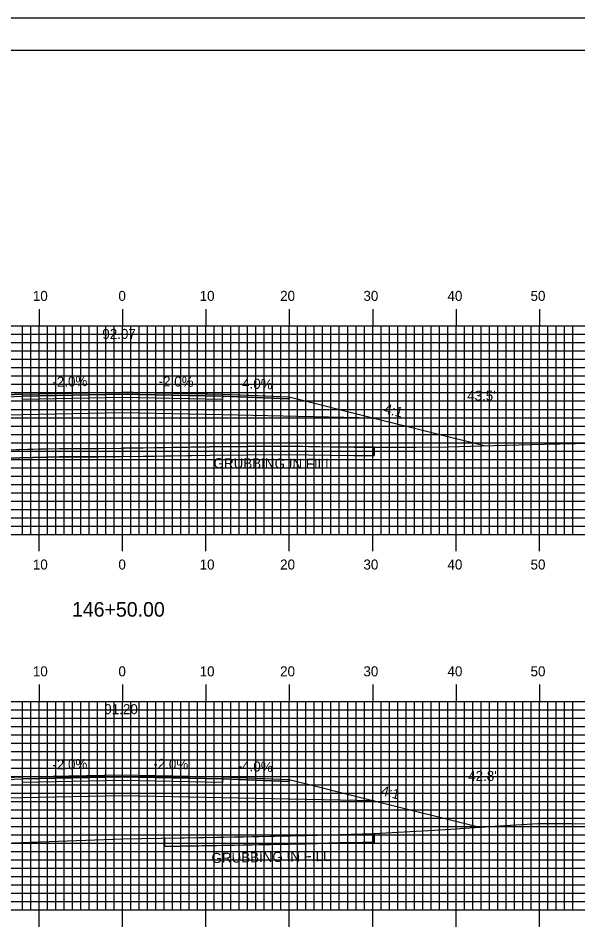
# Model space of a CAD drawing. Extents: x 1777531 to 1777875, y 442591 to 442811.
# Drawn here: x 1777684.8 to 1777751.9, y 442701.2 to 442810.5 of the extents above; entities that cross this region are included whole.
import ezdxf

# ---------------------------------------------------------------- set-up
doc = ezdxf.new("R2010")
doc.units = 0
for name, color, linetype in [('ANNOTATION', 7, 'Continuous'), ('BORDER', 7, 'Continuous'), ('D_Roadway_Centerline', 7, 'Continuous'), ('D_Roadway_Centerline_Text', 7, 'Continuous'), ('D_Roadway_Edge_Shoulder', 7, 'Continuous'), ('D_Roadway_Edge_TW', 7, 'Continuous'), ('D_Roadway_Pavement', 7, 'Continuous'), ('D_Roadway_SlopeLines', 7, 'Continuous'), ('D_Roadway_SubGrade', 7, 'Continuous'), ('D_Text_Standard', 7, 'Continuous'), ('GRUBBING IN FILL', 7, 'Continuous'), ('H_V ANNOTATION', 7, 'Continuous'), ('MAJOR', 7, 'Continuous'), ('MINOR', 7, 'Continuous'), ('PLOT BOUNDARY', 7, 'Continuous'), ('S_Roadway_Centerline', 7, 'Continuous')]:
    doc.layers.add(name, color=color, linetype=linetype)

msp = doc.modelspace()

# ---------------------------------------------------------------- linework, layer by layer
at = {"layer": 'BORDER'}
msp.add_lwpolyline([(1777547.68, 442596.67), (1777867.68, 442596.67), (1777867.68, 442806.67), (1777547.68, 442806.67)], close=True, dxfattribs=at)
at = {"layer": 'D_Roadway_Centerline'}
for points in [[(1777647.68, 442757.78), (1777665.28, 442762.18), (1777666.08, 442762.38), (1777667.1, 442762.63), (1777677.28, 442765.18), (1777680.02, 442765.29), (1777685.28, 442765.5), (1777697.28, 442765.74), (1777698.56, 442765.71), (1777709.28, 442765.5), (1777713.52, 442765.33), (1777717.28, 442765.18), (1777727.45, 442762.63), (1777740.8, 442759.3)], [(1777645.53, 442711.37), (1777665.28, 442716.3), (1777665.54, 442716.37), (1777667.1, 442716.76), (1777677.28, 442719.3), (1777680.25, 442719.42), (1777685.28, 442719.62), (1777690.81, 442719.73), (1777697.28, 442719.86), (1777697.28, 442719.86), (1777709.28, 442719.62), (1777717.28, 442719.3), (1777727.45, 442716.76), (1777740.11, 442713.59), (1777740.11, 442713.59)]]:
    msp.add_lwpolyline(points, dxfattribs=at)
at = {"layer": 'D_Roadway_Edge_Shoulder'}
for points in [[(1777685.28, 442765.5), (1777677.28, 442765.18), (1777677.28, 442764.93), (1777685.28, 442765.25)], [(1777709.28, 442765.5), (1777717.28, 442765.18), (1777717.28, 442764.93), (1777709.28, 442765.25)], [(1777685.28, 442719.62), (1777677.28, 442719.3), (1777677.28, 442719.05), (1777685.28, 442719.37)], [(1777709.28, 442719.62), (1777717.28, 442719.3), (1777717.28, 442719.05), (1777709.28, 442719.37)]]:
    msp.add_lwpolyline(points, close=True, dxfattribs=at)
at = {"layer": 'D_Roadway_Edge_TW'}
for points in [[(1777685.28, 442765.25), (1777685.28, 442765.5), (1777697.28, 442765.74), (1777709.28, 442765.5), (1777709.28, 442765.25), (1777697.28, 442765.49)], [(1777685.28, 442719.37), (1777685.28, 442719.62), (1777697.28, 442719.86), (1777709.28, 442719.62), (1777709.28, 442719.37), (1777697.28, 442719.61)]]:
    msp.add_lwpolyline(points, close=True, dxfattribs=at)
at = {"layer": 'D_Roadway_Pavement'}
for points in [[(1777685.28, 442764.83), (1777685.28, 442765.25), (1777697.28, 442765.49), (1777709.28, 442765.25), (1777709.28, 442764.83), (1777697.28, 442765.07)], [(1777685.28, 442718.96), (1777685.28, 442719.37), (1777697.28, 442719.61), (1777709.28, 442719.37), (1777709.28, 442718.96), (1777697.28, 442719.2)]]:
    msp.add_lwpolyline(points, close=True, dxfattribs=at)
at = {"layer": 'D_Roadway_SlopeLines'}
for points in [[(1777717.28, 442765.18), (1777727.45, 442762.63), (1777740.8, 442759.3)], [(1777717.28, 442719.3), (1777727.45, 442716.76), (1777740.11, 442713.59)]]:
    msp.add_lwpolyline(points, dxfattribs=at)
at = {"layer": 'D_Roadway_SubGrade'}
for points in [[(1777685.28, 442763), (1777667.1, 442762.63), (1777677.28, 442765.18), (1777677.28, 442764.93), (1777685.28, 442765.25), (1777697.28, 442765.49), (1777709.28, 442765.25), (1777717.28, 442764.93), (1777717.28, 442765.18), (1777727.45, 442762.63), (1777709.28, 442763), (1777697.28, 442763.24)], [(1777685.28, 442717.12), (1777667.1, 442716.76), (1777677.28, 442719.3), (1777677.28, 442719.05), (1777685.28, 442719.37), (1777697.28, 442719.61), (1777709.28, 442719.37), (1777717.28, 442719.05), (1777717.28, 442719.3), (1777727.45, 442716.76), (1777709.28, 442717.12), (1777697.28, 442717.36)]]:
    msp.add_lwpolyline(points, close=True, dxfattribs=at)
at = {"layer": 'GRUBBING IN FILL'}
for p, q in [((1777727.45, 442759.13), (1777727.45, 442758.13)), ((1777727.45, 442759.13), (1777727.45, 442758.13)), ((1777702.32, 442712.26), (1777702.32, 442711.26)), ((1777702.32, 442712.26), (1777702.32, 442711.26)), ((1777727.45, 442711.76), (1777727.45, 442712.82)), ((1777727.45, 442711.76), (1777727.45, 442712.82))]:
    msp.add_line(p, q, dxfattribs=at)
for points in [[(1777667.1, 442758.15), (1777669.22, 442758.21), (1777675.28, 442758.49), (1777678.54, 442758.68), (1777681.74, 442758.77), (1777687.32, 442758.92), (1777692.07, 442758.98), (1777697.28, 442759.01), (1777697.28, 442758.01), (1777694.46, 442757.97), (1777689.7, 442757.99), (1777681.78, 442757.77), (1777678.58, 442757.68), (1777672.07, 442757.3), (1777667.1, 442757.15)], [(1777667.1, 442758.15), (1777669.22, 442758.21), (1777675.28, 442758.49), (1777678.54, 442758.68), (1777681.74, 442758.77), (1777687.32, 442758.92), (1777692.07, 442758.98), (1777697.28, 442759.01), (1777697.28, 442758.01), (1777694.46, 442757.97), (1777689.7, 442757.99), (1777681.78, 442757.77), (1777678.58, 442757.68), (1777672.07, 442757.3), (1777667.1, 442757.15)], [(1777697.28, 442758.01), (1777701.1, 442758.07), (1777707.74, 442758.17), (1777716.86, 442758.27), (1777725.04, 442758.12), (1777727.45, 442758.13), (1777727.45, 442759.13), (1777725.05, 442759.12), (1777720.96, 442759.19), (1777716.86, 442759.27), (1777712.3, 442759.22), (1777707.73, 442759.17), (1777701.09, 442759.07), (1777697.28, 442759.01)], [(1777697.28, 442758.01), (1777701.1, 442758.07), (1777707.74, 442758.17), (1777716.86, 442758.27), (1777725.04, 442758.12), (1777727.45, 442758.13), (1777727.45, 442759.13), (1777725.05, 442759.12), (1777720.96, 442759.19), (1777716.86, 442759.27), (1777712.3, 442759.22), (1777707.73, 442759.17), (1777701.09, 442759.07), (1777697.28, 442759.01)], [(1777702.32, 442712.26), (1777711.78, 442712.44), (1777719.29, 442712.59), (1777727.43, 442712.82), (1777727.45, 442712.82), (1777727.45, 442711.76), (1777723.38, 442711.7), (1777719.31, 442711.59), (1777711.8, 442711.44), (1777704.28, 442711.3), (1777702.32, 442711.26)], [(1777702.32, 442712.26), (1777711.78, 442712.44), (1777719.29, 442712.59), (1777727.43, 442712.82), (1777727.45, 442712.82), (1777727.45, 442711.76), (1777723.38, 442711.7), (1777719.31, 442711.59), (1777711.8, 442711.44), (1777704.28, 442711.3), (1777702.32, 442711.26)]]:
    msp.add_lwpolyline(points, close=True, dxfattribs=at)
for points in [[(1777667.1, 442757.15), (1777672.07, 442757.3), (1777678.58, 442757.68), (1777684.98, 442757.85), (1777689.7, 442757.99), (1777694.46, 442757.97), (1777707.74, 442758.17), (1777716.86, 442758.27), (1777725.04, 442758.12), (1777727.45, 442758.13)], [(1777667.1, 442757.15), (1777672.07, 442757.3), (1777678.58, 442757.68), (1777684.98, 442757.85), (1777689.7, 442757.99), (1777694.46, 442757.97), (1777707.74, 442758.17), (1777716.86, 442758.27), (1777725.04, 442758.12), (1777727.45, 442758.13)], [(1777702.32, 442711.26), (1777704.28, 442711.3), (1777719.31, 442711.59), (1777727.45, 442711.82)], [(1777702.32, 442711.26), (1777704.28, 442711.3), (1777719.31, 442711.59), (1777727.45, 442711.82)]]:
    msp.add_lwpolyline(points, dxfattribs=at)
at = {"layer": 'MAJOR'}
for p, q in [((1777687.28, 442775.67), (1777687.28, 442773.67)), ((1777697.28, 442775.67), (1777697.28, 442773.67)), ((1777707.28, 442775.67), (1777707.28, 442773.67)), ((1777717.28, 442775.67), (1777717.28, 442773.67)), ((1777727.28, 442775.67), (1777727.28, 442773.67)), ((1777737.28, 442775.67), (1777737.28, 442773.67)), ((1777747.28, 442775.67), (1777747.28, 442773.67)), ((1777557.28, 442773.67), (1777837.28, 442773.67)), ((1777557.28, 442773.67), (1777837.28, 442773.67)), ((1777687.28, 442748.67), (1777687.28, 442773.67)), ((1777697.28, 442748.67), (1777697.28, 442773.67)), ((1777707.28, 442748.67), (1777707.28, 442773.67)), ((1777717.28, 442748.67), (1777717.28, 442773.67)), ((1777727.28, 442748.67), (1777727.28, 442773.67)), ((1777737.28, 442748.67), (1777737.28, 442773.67)), ((1777747.28, 442748.67), (1777747.28, 442773.67)), ((1777557.28, 442768.67), (1777837.28, 442768.67)), ((1777557.28, 442763.67), (1777837.28, 442763.67)), ((1777557.28, 442758.67), (1777837.28, 442758.67)), ((1777557.28, 442753.67), (1777837.28, 442753.67)), ((1777557.28, 442748.67), (1777837.28, 442748.67)), ((1777557.28, 442748.67), (1777837.28, 442748.67)), ((1777687.28, 442746.66), (1777687.28, 442748.67)), ((1777697.28, 442746.66), (1777697.28, 442748.67)), ((1777707.28, 442746.66), (1777707.28, 442748.67)), ((1777717.28, 442746.66), (1777717.28, 442748.67)), ((1777727.28, 442746.66), (1777727.28, 442748.67)), ((1777737.28, 442746.66), (1777737.28, 442748.67)), ((1777747.28, 442746.66), (1777747.28, 442748.67)), ((1777687.28, 442730.67), (1777687.28, 442728.67)), ((1777697.28, 442730.67), (1777697.28, 442728.67)), ((1777707.28, 442730.67), (1777707.28, 442728.67)), ((1777717.28, 442730.67), (1777717.28, 442728.67)), ((1777727.28, 442730.67), (1777727.28, 442728.67)), ((1777737.28, 442730.67), (1777737.28, 442728.67)), ((1777747.28, 442730.67), (1777747.28, 442728.67)), ((1777557.28, 442728.67), (1777837.28, 442728.67)), ((1777557.28, 442728.67), (1777837.28, 442728.67)), ((1777687.28, 442703.67), (1777687.28, 442728.67)), ((1777697.28, 442703.67), (1777697.28, 442728.67)), ((1777707.28, 442703.67), (1777707.28, 442728.67)), ((1777717.28, 442703.67), (1777717.28, 442728.67)), ((1777727.28, 442703.67), (1777727.28, 442728.67)), ((1777737.28, 442703.67), (1777737.28, 442728.67)), ((1777747.28, 442703.67), (1777747.28, 442728.67)), ((1777557.28, 442723.67), (1777837.28, 442723.67)), ((1777557.28, 442718.67), (1777837.28, 442718.67)), ((1777557.28, 442713.67), (1777837.28, 442713.67)), ((1777557.28, 442708.67), (1777837.28, 442708.67)), ((1777557.28, 442703.67), (1777837.28, 442703.67)), ((1777557.28, 442703.67), (1777837.28, 442703.67)), ((1777687.28, 442701.66), (1777687.28, 442703.67)), ((1777697.28, 442701.66), (1777697.28, 442703.67)), ((1777707.28, 442701.66), (1777707.28, 442703.67)), ((1777717.28, 442701.66), (1777717.28, 442703.67)), ((1777727.28, 442701.66), (1777727.28, 442703.67)), ((1777737.28, 442701.66), (1777737.28, 442703.67)), ((1777747.28, 442701.66), (1777747.28, 442703.67))]:
    msp.add_line(p, q, dxfattribs=at)
at = {"layer": 'MINOR'}
for p, q in [((1777685.28, 442748.67), (1777685.28, 442773.67)), ((1777686.28, 442748.67), (1777686.28, 442773.67)), ((1777688.28, 442748.67), (1777688.28, 442773.67)), ((1777689.28, 442748.67), (1777689.28, 442773.67)), ((1777690.28, 442748.67), (1777690.28, 442773.67)), ((1777691.28, 442748.67), (1777691.28, 442773.67)), ((1777692.28, 442748.67), (1777692.28, 442773.67)), ((1777693.28, 442748.67), (1777693.28, 442773.67)), ((1777694.28, 442748.67), (1777694.28, 442773.67)), ((1777695.28, 442748.67), (1777695.28, 442773.67)), ((1777696.28, 442748.67), (1777696.28, 442773.67)), ((1777698.28, 442748.67), (1777698.28, 442773.67)), ((1777699.28, 442748.67), (1777699.28, 442773.67)), ((1777700.28, 442748.67), (1777700.28, 442773.67)), ((1777701.28, 442748.67), (1777701.28, 442773.67)), ((1777702.28, 442748.67), (1777702.28, 442773.67)), ((1777703.28, 442748.67), (1777703.28, 442773.67)), ((1777704.28, 442748.67), (1777704.28, 442773.67)), ((1777705.28, 442748.67), (1777705.28, 442773.67)), ((1777706.28, 442748.67), (1777706.28, 442773.67)), ((1777708.28, 442748.67), (1777708.28, 442773.67)), ((1777709.28, 442748.67), (1777709.28, 442773.67)), ((1777710.28, 442748.67), (1777710.28, 442773.67)), ((1777711.28, 442748.67), (1777711.28, 442773.67)), ((1777712.28, 442748.67), (1777712.28, 442773.67)), ((1777713.28, 442748.67), (1777713.28, 442773.67)), ((1777714.28, 442748.67), (1777714.28, 442773.67)), ((1777715.28, 442748.67), (1777715.28, 442773.67)), ((1777716.28, 442748.67), (1777716.28, 442773.67)), ((1777718.28, 442748.67), (1777718.28, 442773.67)), ((1777719.28, 442748.67), (1777719.28, 442773.67)), ((1777720.28, 442748.67), (1777720.28, 442773.67)), ((1777721.28, 442748.67), (1777721.28, 442773.67)), ((1777722.28, 442748.67), (1777722.28, 442773.67)), ((1777723.28, 442748.67), (1777723.28, 442773.67)), ((1777724.28, 442748.67), (1777724.28, 442773.67)), ((1777725.28, 442748.67), (1777725.28, 442773.67)), ((1777726.28, 442748.67), (1777726.28, 442773.67)), ((1777728.28, 442748.67), (1777728.28, 442773.67)), ((1777729.28, 442748.67), (1777729.28, 442773.67)), ((1777730.28, 442748.67), (1777730.28, 442773.67)), ((1777731.28, 442748.67), (1777731.28, 442773.67)), ((1777732.28, 442748.67), (1777732.28, 442773.67)), ((1777733.28, 442748.67), (1777733.28, 442773.67)), ((1777734.28, 442748.67), (1777734.28, 442773.67)), ((1777735.28, 442748.67), (1777735.28, 442773.67)), ((1777736.28, 442748.67), (1777736.28, 442773.67)), ((1777738.28, 442748.67), (1777738.28, 442773.67)), ((1777739.28, 442748.67), (1777739.28, 442773.67)), ((1777740.28, 442748.67), (1777740.28, 442773.67)), ((1777741.28, 442748.67), (1777741.28, 442773.67)), ((1777742.28, 442748.67), (1777742.28, 442773.67)), ((1777743.28, 442748.67), (1777743.28, 442773.67)), ((1777744.28, 442748.67), (1777744.28, 442773.67)), ((1777745.28, 442748.67), (1777745.28, 442773.67)), ((1777746.28, 442748.67), (1777746.28, 442773.67)), ((1777748.28, 442748.67), (1777748.28, 442773.67)), ((1777749.28, 442748.67), (1777749.28, 442773.67)), ((1777750.28, 442748.67), (1777750.28, 442773.67)), ((1777751.28, 442748.67), (1777751.28, 442773.67)), ((1777557.28, 442772.67), (1777837.28, 442772.67)), ((1777557.28, 442771.67), (1777837.28, 442771.67)), ((1777557.28, 442770.67), (1777837.28, 442770.67)), ((1777557.28, 442769.67), (1777837.28, 442769.67)), ((1777557.28, 442767.67), (1777837.28, 442767.67)), ((1777557.28, 442766.67), (1777837.28, 442766.67)), ((1777557.28, 442765.67), (1777837.28, 442765.67)), ((1777557.28, 442764.67), (1777837.28, 442764.67)), ((1777557.28, 442762.67), (1777837.28, 442762.67)), ((1777557.28, 442761.67), (1777837.28, 442761.67)), ((1777557.28, 442760.67), (1777837.28, 442760.67)), ((1777557.28, 442759.67), (1777837.28, 442759.67)), ((1777557.28, 442757.67), (1777837.28, 442757.67)), ((1777557.28, 442756.67), (1777837.28, 442756.67)), ((1777557.28, 442755.67), (1777837.28, 442755.67)), ((1777557.28, 442754.67), (1777837.28, 442754.67)), ((1777557.28, 442752.67), (1777837.28, 442752.67)), ((1777557.28, 442751.67), (1777837.28, 442751.67)), ((1777557.28, 442750.67), (1777837.28, 442750.67)), ((1777557.28, 442749.67), (1777837.28, 442749.67)), ((1777685.28, 442703.67), (1777685.28, 442728.67)), ((1777686.28, 442703.67), (1777686.28, 442728.67)), ((1777688.28, 442703.67), (1777688.28, 442728.67)), ((1777689.28, 442703.67), (1777689.28, 442728.67)), ((1777690.28, 442703.67), (1777690.28, 442728.67)), ((1777691.28, 442703.67), (1777691.28, 442728.67)), ((1777692.28, 442703.67), (1777692.28, 442728.67)), ((1777693.28, 442703.67), (1777693.28, 442728.67)), ((1777694.28, 442703.67), (1777694.28, 442728.67)), ((1777695.28, 442703.67), (1777695.28, 442728.67)), ((1777696.28, 442703.67), (1777696.28, 442728.67)), ((1777698.28, 442703.67), (1777698.28, 442728.67)), ((1777699.28, 442703.67), (1777699.28, 442728.67)), ((1777700.28, 442703.67), (1777700.28, 442728.67)), ((1777701.28, 442703.67), (1777701.28, 442728.67)), ((1777702.28, 442703.67), (1777702.28, 442728.67)), ((1777703.28, 442703.67), (1777703.28, 442728.67)), ((1777704.28, 442703.67), (1777704.28, 442728.67)), ((1777705.28, 442703.67), (1777705.28, 442728.67)), ((1777706.28, 442703.67), (1777706.28, 442728.67)), ((1777708.28, 442703.67), (1777708.28, 442728.67)), ((1777709.28, 442703.67), (1777709.28, 442728.67)), ((1777710.28, 442703.67), (1777710.28, 442728.67)), ((1777711.28, 442703.67), (1777711.28, 442728.67)), ((1777712.28, 442703.67), (1777712.28, 442728.67)), ((1777713.28, 442703.67), (1777713.28, 442728.67)), ((1777714.28, 442703.67), (1777714.28, 442728.67)), ((1777715.28, 442703.67), (1777715.28, 442728.67)), ((1777716.28, 442703.67), (1777716.28, 442728.67)), ((1777718.28, 442703.67), (1777718.28, 442728.67)), ((1777719.28, 442703.67), (1777719.28, 442728.67)), ((1777720.28, 442703.67), (1777720.28, 442728.67)), ((1777721.28, 442703.67), (1777721.28, 442728.67)), ((1777722.28, 442703.67), (1777722.28, 442728.67)), ((1777723.28, 442703.67), (1777723.28, 442728.67)), ((1777724.28, 442703.67), (1777724.28, 442728.67)), ((1777725.28, 442703.67), (1777725.28, 442728.67)), ((1777726.28, 442703.67), (1777726.28, 442728.67)), ((1777728.28, 442703.67), (1777728.28, 442728.67)), ((1777729.28, 442703.67), (1777729.28, 442728.67)), ((1777730.28, 442703.67), (1777730.28, 442728.67)), ((1777731.28, 442703.67), (1777731.28, 442728.67)), ((1777732.28, 442703.67), (1777732.28, 442728.67)), ((1777733.28, 442703.67), (1777733.28, 442728.67)), ((1777734.28, 442703.67), (1777734.28, 442728.67)), ((1777735.28, 442703.67), (1777735.28, 442728.67)), ((1777736.28, 442703.67), (1777736.28, 442728.67)), ((1777738.28, 442703.67), (1777738.28, 442728.67)), ((1777739.28, 442703.67), (1777739.28, 442728.67)), ((1777740.28, 442703.67), (1777740.28, 442728.67)), ((1777741.28, 442703.67), (1777741.28, 442728.67)), ((1777742.28, 442703.67), (1777742.28, 442728.67)), ((1777743.28, 442703.67), (1777743.28, 442728.67)), ((1777744.28, 442703.67), (1777744.28, 442728.67)), ((1777745.28, 442703.67), (1777745.28, 442728.67)), ((1777746.28, 442703.67), (1777746.28, 442728.67)), ((1777748.28, 442703.67), (1777748.28, 442728.67)), ((1777749.28, 442703.67), (1777749.28, 442728.67)), ((1777750.28, 442703.67), (1777750.28, 442728.67)), ((1777751.28, 442703.67), (1777751.28, 442728.67)), ((1777557.28, 442727.67), (1777837.28, 442727.67)), ((1777557.28, 442726.67), (1777837.28, 442726.67)), ((1777557.28, 442725.67), (1777837.28, 442725.67)), ((1777557.28, 442724.67), (1777837.28, 442724.67)), ((1777557.28, 442722.67), (1777837.28, 442722.67)), ((1777557.28, 442721.67), (1777837.28, 442721.67)), ((1777557.28, 442720.67), (1777837.28, 442720.67)), ((1777557.28, 442719.67), (1777837.28, 442719.67)), ((1777557.28, 442717.67), (1777837.28, 442717.67)), ((1777557.28, 442716.67), (1777837.28, 442716.67)), ((1777557.28, 442715.67), (1777837.28, 442715.67)), ((1777557.28, 442714.67), (1777837.28, 442714.67)), ((1777557.28, 442712.67), (1777837.28, 442712.67)), ((1777557.28, 442711.67), (1777837.28, 442711.67)), ((1777557.28, 442710.67), (1777837.28, 442710.67)), ((1777557.28, 442709.67), (1777837.28, 442709.67)), ((1777557.28, 442707.67), (1777837.28, 442707.67)), ((1777557.28, 442706.67), (1777837.28, 442706.67)), ((1777557.28, 442705.67), (1777837.28, 442705.67)), ((1777557.28, 442704.67), (1777837.28, 442704.67))]:
    msp.add_line(p, q, dxfattribs=at)
at = {"layer": 'PLOT BOUNDARY'}
msp.add_lwpolyline([(1777531.49, 442590.55), (1777871.49, 442590.55), (1777871.49, 442810.55), (1777531.49, 442810.55)], close=True, dxfattribs=at)
at = {"layer": 'S_Roadway_Centerline'}
for points in [[(1777626.02, 442757.69), (1777642.13, 442757.73), (1777648.89, 442757.79), (1777654.97, 442757.95), (1777660.83, 442757.95), (1777666.42, 442758.13), (1777672.02, 442758.3), (1777678.54, 442758.68), (1777684.95, 442758.85), (1777689.69, 442758.99), (1777694.45, 442758.97), (1777707.73, 442759.17), (1777716.86, 442759.27), (1777725.05, 442759.12), (1777732.48, 442759.14), (1777736.36, 442759.18), (1777740.31, 442759.28), (1777747.89, 442759.49), (1777755.31, 442759.67)], [(1777629.31, 442710.62), (1777641.65, 442711.33), (1777650.59, 442711.41), (1777654.25, 442711.39), (1777664.71, 442711.51), (1777673.36, 442711.39), (1777676.76, 442711.51), (1777680.73, 442711.58), (1777697.29, 442712.17), (1777704.26, 442712.3), (1777719.29, 442712.59), (1777727.43, 442712.82), (1777735.4, 442713.28), (1777743.13, 442713.8), (1777747.14, 442714.02), (1777751.12, 442714.04), (1777758.7, 442713.92)]]:
    msp.add_lwpolyline(points, dxfattribs=at)

# ---------------------------------------------------------------- texts
at = {"layer": 'ANNOTATION'}
for s, rotation, p in [('-2.0%', 1.1458, (1777688.88, 442766.37)), ('-2.0%', 358.8542, (1777701.6, 442766.45)), ('-4.0%', 357.7093, (1777711.07, 442766.23)), ('4:1', 345.9646, (1777728.55, 442763.22)), ('-2.0%', 1.1458, (1777688.88, 442720.49)), ('-2.0%', 358.8542, (1777700.96, 442720.59)), ('-4.0%', 357.7095, (1777711.07, 442720.35)), ('4:1', 345.9646, (1777728.2, 442717.43))]:
    msp.add_text(s, height=1.2, rotation=rotation, dxfattribs=at).set_placement(p)
at = {"layer": 'D_Roadway_Centerline'}
for s, p in [('C', (1777697.27, 442765.74)), ('L', (1777697.28, 442765.73)), ('C', (1777697.27, 442719.86)), ('L', (1777697.28, 442719.85))]:
    msp.add_text(s, height=0.0146, dxfattribs=at).set_placement(p)
at = {"layer": 'D_Roadway_Centerline_Text'}
for s, p in [('92.07', (1777694.86, 442772.11)), ('91.20', (1777695.1, 442727.13))]:
    msp.add_text(s, height=1.2, dxfattribs=at).set_placement(p)
at = {"layer": 'D_Text_Standard'}
for s, p in [("43.5'", (1777738.61, 442764.71)), ("42.8'", (1777738.73, 442719.13))]:
    msp.add_text(s, height=1.2, dxfattribs=at).set_placement(p)
at = {"layer": 'GRUBBING IN FILL'}
for rotation, p in [(359.6955, (1777708.2, 442756.62)), (0.9972, (1777707.96, 442709.29))]:
    msp.add_text('GRUBBING IN FILL', height=1.2, rotation=rotation, dxfattribs=at).set_placement(p)
at = {"layer": 'H_V ANNOTATION'}
for s, height, p in [('10', 1.2, (1777686.53, 442776.67)), ('0', 1.2, (1777696.79, 442776.67)), ('10', 1.2, (1777706.53, 442776.67)), ('20', 1.2, (1777716.18, 442776.67)), ('30', 1.2, (1777726.17, 442776.67)), ('40', 1.2, (1777736.25, 442776.67)), ('50', 1.2, (1777746.21, 442776.67)), ('10', 1.2, (1777686.53, 442744.47)), ('0', 1.2, (1777696.79, 442744.47)), ('10', 1.2, (1777706.53, 442744.47)), ('20', 1.2, (1777716.18, 442744.47)), ('30', 1.2, (1777726.17, 442744.47)), ('40', 1.2, (1777736.25, 442744.47)), ('50', 1.2, (1777746.21, 442744.47)), ('146+50.00', 1.75, (1777691.22, 442738.82)), ('10', 1.2, (1777686.53, 442731.67)), ('0', 1.2, (1777696.79, 442731.67)), ('10', 1.2, (1777706.53, 442731.67)), ('20', 1.2, (1777716.18, 442731.67)), ('30', 1.2, (1777726.17, 442731.67)), ('40', 1.2, (1777736.25, 442731.67)), ('50', 1.2, (1777746.21, 442731.67))]:
    msp.add_text(s, height=height, dxfattribs=at).set_placement(p)

doc.saveas('drawing.dxf')
